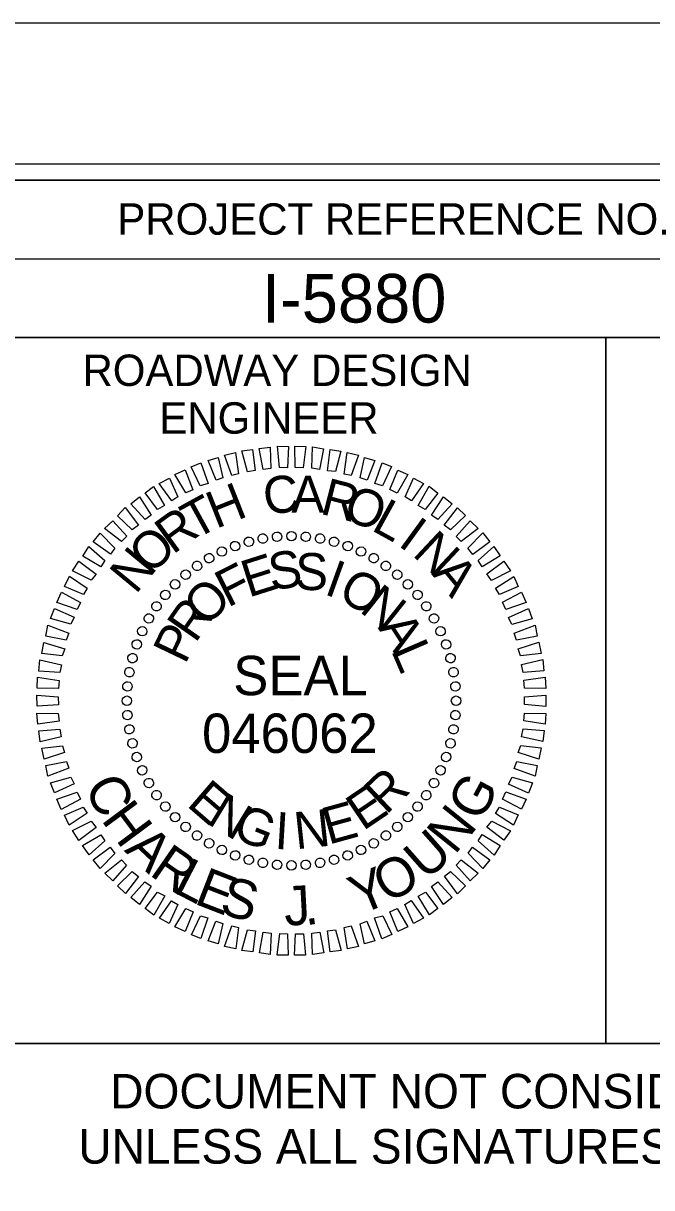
# Model space of a CAD drawing. Extents: x 1648862 to 1650889, y 802691 to 803791.
# Drawn here: x 1650336.5 to 1650436.6, y 803605.5 to 803791 of the extents above; entities that cross this region are included whole.
import ezdxf

# ---------------------------------------------------------------- set-up
doc = ezdxf.new("R2010")
doc.units = 0
for name, color, linetype in [('Default', 7, 'Continuous'), ('Old_Level_2', 7, 'Continuous'), ('Sheet Cutting Line CELL', 7, 'Continuous'), ('Sheet Data Field CELL', 7, 'Continuous'), ('Sheet Plot Border Inside CELL', 7, 'Continuous'), ('Sheet Plot Border Outside CELL', 7, 'Continuous'), ('Sheet Profile CELL', 7, 'Continuous'), ('Sheet Profile Grid Major CELL', 7, 'Continuous'), ('Sheet Sticker Exception Certification CELL', 7, 'Continuous')]:
    doc.layers.add(name, color=color, linetype=linetype)

msp = doc.modelspace()

# ---------------------------------------------------------------- linework, layer by layer
at = {"layer": 'Old_Level_2'}
for p, q in [((1650376.9, 803709.25), (1650376.9, 803709.25)), ((1650379.2, 803709.34), (1650379.2, 803709.34)), ((1650381.5, 803709.22), (1650381.5, 803709.22)), ((1650370.18, 803707.77), (1650370.18, 803707.77)), ((1650372.36, 803708.44), (1650372.36, 803708.44)), ((1650374.65, 803708.89), (1650374.65, 803708.89)), ((1650383.75, 803708.9), (1650383.75, 803708.9)), ((1650385.96, 803708.46), (1650385.96, 803708.46)), ((1650388.17, 803707.77), (1650388.17, 803707.77)), ((1650366.08, 803705.82), (1650366.08, 803705.82)), ((1650368.1, 803706.9), (1650368.1, 803706.9)), ((1650390.27, 803706.87), (1650390.27, 803706.87)), ((1650392.33, 803705.86), (1650392.33, 803705.86)), ((1650364.11, 803704.58), (1650364.11, 803704.58)), ((1650394.24, 803704.58), (1650394.24, 803704.58)), ((1650362.31, 803703.24), (1650362.31, 803703.24)), ((1650396.09, 803703.2), (1650396.09, 803703.2)), ((1650359.07, 803699.99), (1650359.07, 803699.99)), ((1650360.61, 803701.64), (1650360.61, 803701.64)), ((1650397.74, 803701.66), (1650397.74, 803701.66)), ((1650399.34, 803699.96), (1650399.34, 803699.96)), ((1650357.69, 803698.14), (1650357.69, 803698.14)), ((1650400.68, 803698.16), (1650400.68, 803698.16)), ((1650356.42, 803696.23), (1650356.42, 803696.23)), ((1650401.91, 803696.19), (1650401.91, 803696.19)), ((1650355.41, 803694.18), (1650355.41, 803694.18)), ((1650402.99, 803694.17), (1650402.99, 803694.17)), ((1650354.5, 803692.07), (1650354.5, 803692.07)), ((1650403.87, 803692.09), (1650403.87, 803692.09)), ((1650353.81, 803689.86), (1650353.81, 803689.86)), ((1650404.53, 803689.91), (1650404.53, 803689.91)), ((1650353.37, 803687.66), (1650353.37, 803687.66)), ((1650404.99, 803687.62), (1650404.99, 803687.62)), ((1650353.05, 803685.4), (1650353.05, 803685.4)), ((1650405.34, 803685.37), (1650405.34, 803685.37)), ((1650352.93, 803683.1), (1650352.93, 803683.1)), ((1650379.18, 803683.09), (1650379.18, 803683.09)), ((1650405.44, 803683.07), (1650405.44, 803683.07)), ((1650353.02, 803680.8), (1650353.02, 803680.8)), ((1650405.32, 803680.77), (1650405.32, 803680.77)), ((1650353.38, 803678.56), (1650353.38, 803678.56)), ((1650404.99, 803678.52), (1650404.99, 803678.52)), ((1650353.84, 803676.26), (1650353.84, 803676.26)), ((1650404.56, 803676.31), (1650404.56, 803676.31)), ((1650354.5, 803674.08), (1650354.5, 803674.08)), ((1650403.87, 803674.1), (1650403.87, 803674.1)), ((1650355.37, 803672), (1650355.37, 803672)), ((1650402.96, 803672), (1650402.96, 803672)), ((1650356.46, 803669.98), (1650356.46, 803669.98)), ((1650401.95, 803669.94), (1650401.95, 803669.94)), ((1650357.69, 803668.02), (1650357.69, 803668.02)), ((1650400.68, 803668.03), (1650400.68, 803668.03)), ((1650359.03, 803666.21), (1650359.03, 803666.21)), ((1650399.3, 803666.18), (1650399.3, 803666.18)), ((1650360.63, 803664.51), (1650360.63, 803664.51)), ((1650362.28, 803662.97), (1650362.28, 803662.97)), ((1650396.06, 803662.93), (1650396.06, 803662.93)), ((1650397.76, 803664.53), (1650397.76, 803664.53)), ((1650364.13, 803661.59), (1650364.13, 803661.59)), ((1650394.25, 803661.59), (1650394.25, 803661.59)), ((1650366.04, 803660.32), (1650366.04, 803660.32)), ((1650368.09, 803659.31), (1650368.09, 803659.31)), ((1650390.27, 803659.28), (1650390.27, 803659.28)), ((1650392.29, 803660.36), (1650392.29, 803660.36)), ((1650370.2, 803658.4), (1650370.2, 803658.4)), ((1650372.41, 803657.71), (1650372.41, 803657.71)), ((1650374.61, 803657.28), (1650374.61, 803657.28)), ((1650383.71, 803657.28), (1650383.71, 803657.28)), ((1650386.01, 803657.74), (1650386.01, 803657.74)), ((1650388.19, 803658.4), (1650388.19, 803658.4)), ((1650376.87, 803656.95), (1650376.87, 803656.95)), ((1650379.17, 803656.83), (1650379.17, 803656.83)), ((1650381.47, 803656.93), (1650381.47, 803656.93))]:
    msp.add_line(p, q, dxfattribs=at)
for points in [[(1650369.67, 803718.95), (1650368.51, 803722.23), (1650370.28, 803722.62), (1650370.76, 803719.23)], [(1650372.17, 803719.57), (1650371.27, 803722.9), (1650373, 803723.09), (1650373.42, 803719.75)], [(1650374.67, 803719.93), (1650374.04, 803723.26), (1650375.81, 803723.5), (1650375.92, 803720.11)], [(1650377.28, 803720.24), (1650376.96, 803723.63), (1650378.69, 803723.61), (1650378.54, 803720.21)], [(1650379.79, 803720.23), (1650379.73, 803723.63), (1650381.46, 803723.6), (1650381.05, 803720.2)], [(1650382.41, 803720.12), (1650382.56, 803723.52), (1650384.29, 803723.23), (1650383.67, 803719.93)], [(1650384.92, 803719.74), (1650385.34, 803723.1), (1650387.07, 803722.86), (1650386.18, 803719.61)], [(1650387.6, 803719.21), (1650388.06, 803722.62), (1650389.85, 803722.23), (1650388.7, 803718.97)], [(1650364.62, 803717.35), (1650363.21, 803720.36), (1650364.77, 803721.01), (1650365.92, 803717.68)], [(1650367.17, 803718.23), (1650365.91, 803721.34), (1650367.53, 803721.84), (1650368.26, 803718.61)], [(1650390.12, 803718.58), (1650390.85, 803721.83), (1650392.48, 803721.34), (1650391.23, 803718.23)], [(1650392.49, 803717.68), (1650393.64, 803720.99), (1650395.11, 803720.39), (1650393.7, 803717.33)], [(1650360.12, 803714.92), (1650358.13, 803717.71), (1650359.74, 803718.57), (1650361.1, 803715.56)], [(1650362.34, 803716.21), (1650360.62, 803719.11), (1650362.23, 803719.87), (1650363.48, 803716.7)], [(1650394.86, 803716.72), (1650396.11, 803719.83), (1650397.75, 803719.13), (1650396.02, 803716.17)], [(1650397.29, 803715.56), (1650398.65, 803718.57), (1650400.23, 803717.71), (1650398.29, 803714.95)], [(1650357.84, 803713.57), (1650355.86, 803716.2), (1650357.2, 803717.22), (1650358.98, 803714.22)], [(1650399.35, 803714.19), (1650401.13, 803717.25), (1650402.51, 803716.18), (1650400.51, 803713.58)], [(1650355.88, 803711.97), (1650353.59, 803714.44), (1650354.98, 803715.56), (1650356.86, 803712.66)], [(1650401.52, 803712.66), (1650403.41, 803715.57), (1650404.79, 803714.44), (1650402.53, 803711.94)], [(1650353.82, 803710.31), (1650351.48, 803712.57), (1650352.71, 803713.85), (1650354.8, 803711.06)], [(1650403.54, 803711.07), (1650405.63, 803713.83), (1650406.91, 803712.59), (1650404.54, 803710.3)], [(1650352.12, 803708.45), (1650349.42, 803710.55), (1650350.71, 803711.77), (1650352.94, 803709.3)], [(1650405.45, 803709.27), (1650407.66, 803711.77), (1650408.93, 803710.54), (1650406.25, 803708.45)], [(1650350.33, 803706.43), (1650347.57, 803708.42), (1650348.7, 803709.8), (1650351.04, 803707.38)], [(1650407.31, 803707.42), (1650409.68, 803709.82), (1650410.8, 803708.43), (1650408.06, 803706.39)], [(1650348.79, 803704.42), (1650345.94, 803706.14), (1650346.91, 803707.68), (1650349.46, 803705.42)], [(1650408.92, 803705.41), (1650411.44, 803707.65), (1650412.46, 803706.15), (1650409.56, 803704.43)], [(1650347.26, 803702.3), (1650344.31, 803703.81), (1650345.33, 803705.3), (1650348.08, 803703.25)], [(1650410.31, 803703.29), (1650413.05, 803705.33), (1650414.07, 803703.78), (1650411.06, 803702.26)], [(1650346.05, 803700.03), (1650343.04, 803701.28), (1650343.8, 803702.92), (1650346.66, 803701.03)], [(1650411.71, 803701.02), (1650414.61, 803702.9), (1650415.32, 803701.29), (1650412.36, 803700.03)], [(1650345.04, 803697.6), (1650341.78, 803698.75), (1650342.54, 803700.38), (1650345.55, 803698.76)], [(1650412.8, 803698.79), (1650415.86, 803700.41), (1650416.56, 803698.75), (1650413.34, 803697.65)], [(1650344.04, 803695.29), (1650340.78, 803696.17), (1650341.43, 803697.8), (1650344.59, 803696.39)], [(1650413.78, 803696.35), (1650416.95, 803697.76), (1650417.55, 803696.15), (1650414.32, 803695.26)], [(1650343.3, 803692.76), (1650340.04, 803693.39), (1650340.38, 803695.12), (1650343.7, 803693.87)], [(1650414.66, 803693.85), (1650417.99, 803695.11), (1650418.33, 803693.39), (1650415.05, 803692.76)], [(1650342.66, 803690.24), (1650339.41, 803690.6), (1650339.75, 803692.39), (1650343.06, 803691.35)], [(1650415.33, 803691.35), (1650418.61, 803692.4), (1650418.95, 803690.63), (1650415.67, 803690.26)], [(1650342.29, 803687.57), (1650338.94, 803687.82), (1650339.12, 803689.6), (1650342.53, 803688.83)], [(1650415.85, 803688.85), (1650419.23, 803689.64), (1650419.42, 803687.87), (1650416.08, 803687.6)], [(1650342.07, 803685.05), (1650338.67, 803685.1), (1650338.75, 803686.83), (1650342.15, 803686.31)], [(1650416.21, 803686.35), (1650419.6, 803686.82), (1650419.73, 803685.05), (1650416.33, 803685.09)], [(1650342.07, 803682.44), (1650338.67, 803682.22), (1650338.64, 803684), (1650342.04, 803683.69)], [(1650416.3, 803683.73), (1650419.7, 803683.95), (1650419.73, 803682.17), (1650416.33, 803682.48)], [(1650342.16, 803679.83), (1650338.77, 803679.35), (1650338.64, 803681.12), (1650342.04, 803681.08)], [(1650416.3, 803681.12), (1650419.7, 803681.07), (1650419.62, 803679.35), (1650416.21, 803679.86)], [(1650342.52, 803677.32), (1650339.14, 803676.53), (1650338.95, 803678.3), (1650342.29, 803678.57)], [(1650416.08, 803678.61), (1650419.43, 803678.35), (1650419.25, 803676.57), (1650415.84, 803677.35)], [(1650343.04, 803674.82), (1650339.76, 803673.77), (1650339.41, 803675.54), (1650342.7, 803675.91)], [(1650415.71, 803675.93), (1650418.96, 803675.57), (1650418.62, 803673.79), (1650415.31, 803674.83)], [(1650343.71, 803672.32), (1650340.38, 803671.06), (1650340.04, 803672.78), (1650343.32, 803673.41)], [(1650415.07, 803673.41), (1650418.32, 803672.79), (1650417.99, 803671.06), (1650414.67, 803672.31)], [(1650344.59, 803669.83), (1650341.42, 803668.41), (1650340.82, 803670.02), (1650344.04, 803670.92)], [(1650414.33, 803670.89), (1650417.59, 803670), (1650416.94, 803668.37), (1650413.78, 803669.78)], [(1650345.57, 803667.39), (1650342.51, 803665.76), (1650341.8, 803667.42), (1650345.03, 803668.53)], [(1650413.33, 803668.57), (1650416.59, 803667.42), (1650415.83, 803665.79), (1650412.82, 803667.41)], [(1650346.66, 803665.16), (1650343.76, 803663.28), (1650343.05, 803664.88), (1650346.01, 803666.14)], [(1650412.32, 803666.15), (1650415.33, 803664.89), (1650414.57, 803663.26), (1650411.71, 803665.14)], [(1650348.05, 803662.88), (1650345.32, 803660.84), (1650344.3, 803662.4), (1650347.3, 803663.91)], [(1650411.11, 803663.88), (1650414.06, 803662.36), (1650413.04, 803660.88), (1650410.29, 803662.92)], [(1650349.45, 803660.76), (1650346.93, 803658.52), (1650345.91, 803660.02), (1650348.81, 803661.74)], [(1650409.57, 803661.76), (1650412.43, 803660.03), (1650411.46, 803658.5), (1650408.91, 803660.75)], [(1650351.06, 803658.75), (1650348.69, 803656.35), (1650347.57, 803657.75), (1650350.31, 803659.78)], [(1650408.04, 803659.74), (1650410.8, 803657.75), (1650409.67, 803656.37), (1650407.33, 803658.79)], [(1650352.92, 803656.9), (1650350.71, 803654.4), (1650349.44, 803655.63), (1650352.12, 803657.72)], [(1650406.25, 803657.72), (1650408.95, 803655.63), (1650407.66, 803654.4), (1650405.42, 803656.87)], [(1650354.83, 803655.1), (1650352.74, 803652.35), (1650351.46, 803653.58), (1650353.83, 803655.87)], [(1650404.55, 803655.86), (1650406.89, 803653.6), (1650405.66, 803652.33), (1650403.57, 803655.12)], [(1650356.85, 803653.52), (1650354.96, 803650.61), (1650353.58, 803651.73), (1650355.84, 803654.23)], [(1650402.49, 803654.21), (1650404.78, 803651.74), (1650403.39, 803650.61), (1650401.51, 803653.51)], [(1650359.02, 803651.98), (1650357.24, 803648.92), (1650355.86, 803649.99), (1650357.86, 803652.59)], [(1650400.53, 803652.6), (1650402.51, 803649.97), (1650401.17, 803648.95), (1650399.39, 803651.96)], [(1650361.08, 803650.61), (1650359.72, 803647.6), (1650358.14, 803648.46), (1650360.08, 803651.22)], [(1650363.51, 803649.45), (1650362.25, 803646.34), (1650360.62, 803647.04), (1650362.35, 803650)], [(1650396.03, 803649.96), (1650397.75, 803647.06), (1650396.14, 803646.3), (1650394.88, 803649.47)], [(1650398.25, 803651.26), (1650400.24, 803648.47), (1650398.63, 803647.6), (1650397.27, 803650.61)], [(1650365.88, 803648.5), (1650364.73, 803645.18), (1650363.26, 803645.78), (1650364.67, 803648.84)], [(1650368.25, 803647.6), (1650367.52, 803644.34), (1650365.89, 803644.83), (1650367.14, 803647.94)], [(1650391.2, 803647.94), (1650392.46, 803644.83), (1650390.84, 803644.33), (1650390.11, 803647.56)], [(1650393.75, 803648.82), (1650395.16, 803645.82), (1650393.6, 803645.16), (1650392.44, 803648.49)], [(1650370.77, 803646.96), (1650370.3, 803643.55), (1650368.52, 803643.94), (1650369.67, 803647.2)], [(1650373.44, 803646.43), (1650373.03, 803643.08), (1650371.3, 803643.31), (1650372.19, 803646.57)], [(1650375.96, 803646.06), (1650375.81, 803642.65), (1650374.08, 803642.94), (1650374.7, 803646.24)], [(1650383.7, 803646.24), (1650384.33, 803642.91), (1650382.56, 803642.67), (1650382.45, 803646.07)], [(1650386.2, 803646.6), (1650387.1, 803643.27), (1650385.37, 803643.08), (1650384.95, 803646.42)], [(1650388.7, 803647.22), (1650389.86, 803643.95), (1650388.09, 803643.55), (1650387.61, 803646.94)], [(1650378.58, 803645.95), (1650378.64, 803642.55), (1650376.91, 803642.57), (1650377.32, 803645.98)], [(1650381.09, 803645.94), (1650381.41, 803642.54), (1650379.68, 803642.57), (1650379.83, 803645.97)]]:
    msp.add_lwpolyline(points, close=True, dxfattribs=at)
for centre, major_axis in [((1650372.4, 803708.42), (-0.195, 0.727)), ((1650374.63, 803708.92), (-0.131, 0.742)), ((1650376.9, 803709.21), (-0.066, 0.75)), ((1650379.18, 803709.31), (0, 0.753)), ((1650381.47, 803709.21), (0.066, 0.75)), ((1650383.74, 803708.92), (0.131, 0.742)), ((1650385.97, 803708.42), (0.195, 0.727)), ((1650368.1, 803706.86), (-0.318, 0.682)), ((1650370.21, 803707.73), (-0.258, 0.708)), ((1650388.15, 803707.73), (0.258, 0.708)), ((1650390.27, 803706.86), (0.318, 0.682)), ((1650366.07, 803705.8), (-0.376, 0.652)), ((1650392.3, 803705.8), (0.376, 0.652)), ((1650362.33, 803703.18), (-0.484, 0.577)), ((1650364.14, 803704.57), (-0.432, 0.617)), ((1650394.23, 803704.57), (0.432, 0.617)), ((1650396.04, 803703.18), (0.484, 0.577)), ((1650360.64, 803701.63), (-0.532, 0.532)), ((1650397.73, 803701.63), (0.532, 0.532)), ((1650359.09, 803699.95), (-0.577, 0.484)), ((1650399.28, 803699.95), (0.577, 0.484)), ((1650357.7, 803698.13), (-0.617, 0.432)), ((1650400.67, 803698.13), (0.617, 0.432)), ((1650356.47, 803696.2), (-0.652, 0.376)), ((1650401.9, 803696.2), (0.652, 0.376)), ((1650355.41, 803694.17), (-0.682, 0.318)), ((1650402.95, 803694.17), (0.682, 0.318)), ((1650354.54, 803692.06), (-0.708, 0.258)), ((1650403.83, 803692.06), (0.708, 0.258)), ((1650353.85, 803689.87), (-0.727, 0.195)), ((1650404.52, 803689.87), (0.727, 0.195)), ((1650353.36, 803687.64), (-0.742, 0.131)), ((1650405.01, 803687.64), (0.742, 0.131)), ((1650353.06, 803685.37), (-0.75, 0.066)), ((1650405.31, 803685.37), (0.75, 0.066)), ((1650352.96, 803683.09), (-0.753, 0)), ((1650405.41, 803683.09), (0.753, 0)), ((1650353.06, 803680.8), (-0.75, -0.066)), ((1650405.31, 803680.8), (0.75, -0.066)), ((1650353.36, 803678.53), (-0.742, -0.131)), ((1650405.01, 803678.53), (0.742, -0.131)), ((1650353.85, 803676.3), (-0.727, -0.195)), ((1650404.52, 803676.3), (0.727, -0.195)), ((1650354.54, 803674.12), (-0.708, -0.258)), ((1650403.83, 803674.12), (0.708, -0.258)), ((1650355.41, 803672), (-0.682, -0.318)), ((1650402.95, 803672), (0.682, -0.318)), ((1650356.47, 803669.97), (-0.652, -0.376)), ((1650401.9, 803669.97), (0.652, -0.376)), ((1650357.7, 803668.04), (-0.617, -0.432)), ((1650400.67, 803668.04), (0.617, -0.432)), ((1650359.09, 803666.23), (-0.577, -0.484)), ((1650399.28, 803666.23), (0.577, -0.484)), ((1650360.64, 803664.54), (-0.532, -0.532)), ((1650397.73, 803664.54), (0.532, -0.532)), ((1650362.33, 803662.99), (-0.484, -0.577)), ((1650396.04, 803662.99), (0.484, -0.577)), ((1650364.14, 803661.6), (-0.432, -0.617)), ((1650366.07, 803660.37), (-0.376, -0.652)), ((1650392.3, 803660.37), (0.376, -0.652)), ((1650394.23, 803661.6), (0.432, -0.617)), ((1650368.1, 803659.32), (-0.318, -0.682)), ((1650370.21, 803658.44), (-0.258, -0.708)), ((1650388.15, 803658.44), (0.258, -0.708)), ((1650390.27, 803659.32), (0.318, -0.682)), ((1650372.4, 803657.75), (-0.195, -0.727)), ((1650374.63, 803657.26), (-0.131, -0.742)), ((1650376.9, 803656.96), (-0.066, -0.75)), ((1650379.18, 803656.86), (0, -0.753)), ((1650381.47, 803656.96), (0.066, -0.75)), ((1650383.74, 803657.26), (0.131, -0.742)), ((1650385.97, 803657.75), (0.195, -0.727))]:
    msp.add_ellipse(centre, major_axis=major_axis, ratio=0.999708, dxfattribs=at)
at = {"layer": 'Sheet Cutting Line CELL'}
msp.add_line((1650546.28, 803791.02), (1648862.28, 803791.02), dxfattribs=at)
at = {"layer": 'Sheet Plot Border Inside CELL'}
msp.add_lwpolyline([(1648875.28, 802713.47), (1650541.78, 802713.47), (1650541.78, 803768.57), (1648875.28, 803768.57)], close=True, dxfattribs=at)
at = {"layer": 'Sheet Plot Border Outside CELL'}
msp.add_lwpolyline([(1648862.28, 802691.02), (1650546.28, 802691.02), (1650546.28, 803791.02), (1648862.28, 803791.02)], close=True, dxfattribs=at)
at = {"layer": 'Sheet Profile CELL'}
for p, q in [((1650329.23, 803753.47), (1650529.28, 803753.47)), ((1650429.28, 803740.97), (1650429.28, 803628.52))]:
    msp.add_line(p, q, dxfattribs=at)
for points in [[(1650529.28, 803766.02), (1649029.28, 803766.02), (1649029.28, 802716.02), (1650529.28, 802716.02)], [(1650329.23, 803766.02), (1650529.28, 803766.02), (1650529.28, 803740.97), (1650329.23, 803740.97)], [(1650329.23, 803740.97), (1650429.28, 803740.97), (1650429.28, 803628.47), (1650329.23, 803628.47)], [(1650429.28, 803740.97), (1650529.28, 803740.97), (1650529.28, 803628.47), (1650429.28, 803628.47)]]:
    msp.add_lwpolyline(points, close=True, dxfattribs=at)
at = {"layer": 'Sheet Profile Grid Major CELL'}
msp.add_lwpolyline([(1650279.28, 803738.96), (1650279.28, 803266.02), (1650329.28, 803266.02), (1650329.28, 803766.02), (1650355.58, 803766.02)], dxfattribs=at)
at = {"layer": 'Sheet Sticker Exception Certification CELL'}
msp.add_line((1650329.23, 803628.47), (1650529.27, 803628.47), dxfattribs=at)
msp.add_line((1650329.23, 803628.47), (1650529.27, 803628.47), dxfattribs=at)

# ---------------------------------------------------------------- texts
at = {"layer": 'Default'}
for s, rotation, p in [('C', 297.1999, (1650346.07, 803669.36)), ('G', 61.7998, (1650409.3, 803663.59)), ('H', 306.6436, (1650348.76, 803664.11)), ('N', 51.2288, (1650405.21, 803658.4)), ('A', 316.4834, (1650352.45, 803659.18)), ('U', 41.4347, (1650400.63, 803654.33)), ('R', 325.1961, (1650356.38, 803655.41)), ('L', 332.5683, (1650360.12, 803652.71)), ('O', 30.0413, (1650394.53, 803650.66)), ('E', 338.7525, (1650363.5, 803650.83)), ('Y', 22.2426, (1650390, 803648.88)), ('S', 345.7591, (1650367.55, 803649.16)), ('J', 3.0321, (1650378.14, 803647.23)), ('.', 8.214, (1650381.39, 803647.28))]:
    msp.add_text(s, height=6.27, rotation=rotation, dxfattribs=at).set_placement(p)
at = {"layer": 'Old_Level_2'}
for s, rotation, p in [('C', 7.2199, (1650375.06, 803712.67)), ('A', 0.0203, (1650379.18, 803713.05)), ('R', 345.6211, (1650383.58, 803712.92)), ('H', 21.6195, (1650367.15, 803710.44)), ('O', 338.4212, (1650387.1, 803712.2)), ('T', 28.8198, (1650363.78, 803708.65)), ('L', 331.2209, (1650391.73, 803710.34)), ('R', 36.0205, (1650360.27, 803706.29)), ('I', 324.0201, (1650396.01, 803707.91)), ('O', 43.2217, (1650356.72, 803702.99)), ('N', 316.8189, (1650398.29, 803706.33)), ('N', 50.4235, (1650354.36, 803699.91)), ('E', 17.6111, (1650372.36, 803699.49)), ('S', 8.2556, (1650375.95, 803700.65)), ('S', 358.9004, (1650379.71, 803700.77)), ('F', 26.967, (1650369.04, 803697.87)), ('I', 340.1896, (1650384.22, 803700.12)), ('O', 330.8335, (1650386.33, 803699.42)), ('A', 309.6172, (1650401.42, 803703.29)), ('O', 45.6812, (1650365.65, 803694.72)), ('N', 321.4766, (1650389.86, 803697.39)), ('R', 55.0397, (1650363.86, 803692.13)), ('P', 64.3989, (1650362.25, 803688.75)), ('A', 302.7603, (1650392.89, 803694.73)), ('L', 293.4009, (1650394.99, 803691.15)), ('E', 319.2769, (1650362.32, 803666.42)), ('R', 43.4814, (1650394.25, 803664.78)), ('N', 328.634, (1650365.51, 803663.65)), ('E', 34.1241, (1650390.58, 803662.26)), ('E', 15.4118, (1650385.08, 803660.13)), ('G', 337.9902, (1650369.52, 803661.37)), ('I', 356.7012, (1650376.41, 803659.5)), ('N', 6.0564, (1650379.91, 803659.41))]:
    msp.add_text(s, height=5.9, rotation=rotation, dxfattribs=at).set_placement(p)
for s, height, p in [('SEAL', 6.273, (1650369.91, 803683.97)), ('046062', 6.275, (1650364.94, 803674.77))]:
    msp.add_text(s, height=height, dxfattribs=at).set_placement(p)
at = {"layer": 'Sheet Data Field CELL'}
msp.add_text('I-5880', height=7.75, dxfattribs=at).set_placement((1650374.49, 803743.34))
at = {"layer": 'Sheet Profile CELL'}
for s, height, p in [('PROJECT REFERENCE NO.', 5.0001, (1650351.44, 803757.34)), ('ROADWAY DESIGN', 5.0001, (1650345.89, 803733.24)), ('ENGINEER', 5, (1650358.14, 803725.64))]:
    msp.add_text(s, height=height, dxfattribs=at).set_placement(p)
at = {"layer": 'Sheet Sticker Exception Certification CELL'}
for s, p in [('DOCUMENT NOT CONSIDERED FINAL', (1650350.3, 803618.13)), ('DOCUMENT NOT CONSIDERED FINAL', (1650350.3, 803618.13)), ('UNLESS ALL SIGNATURES COMPLETED', (1650345.23, 803609.33)), ('UNLESS ALL SIGNATURES COMPLETED', (1650345.23, 803609.33))]:
    msp.add_text(s, height=5.5, dxfattribs=at).set_placement(p)

doc.saveas('drawing.dxf')
